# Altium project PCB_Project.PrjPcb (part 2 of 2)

## Sheet LLC.SchDoc
size 431 x 279 mm; DrawnBy: Max Wang; DocumentNumber: TIDA-010080; SheetNumber: TIDA-010080; PageSetup: Record=PageOptions¦CenterHorizontal=True¦CenterVertical=True¦PrintScale=1.00¦XCorrection=1.00¦YCorrection=1.00¦PrintKind=0¦BorderSize=5000000¦LeftOffset=0¦BottomOffset=0¦Orientation=2¦PaperLength=1000¦PaperWidth=1000¦Scale=100¦PaperSource=15¦PrintQuality=600¦MediaType=1¦DitherType=10¦PaperKind=Letter¦PrintScaleMode=1
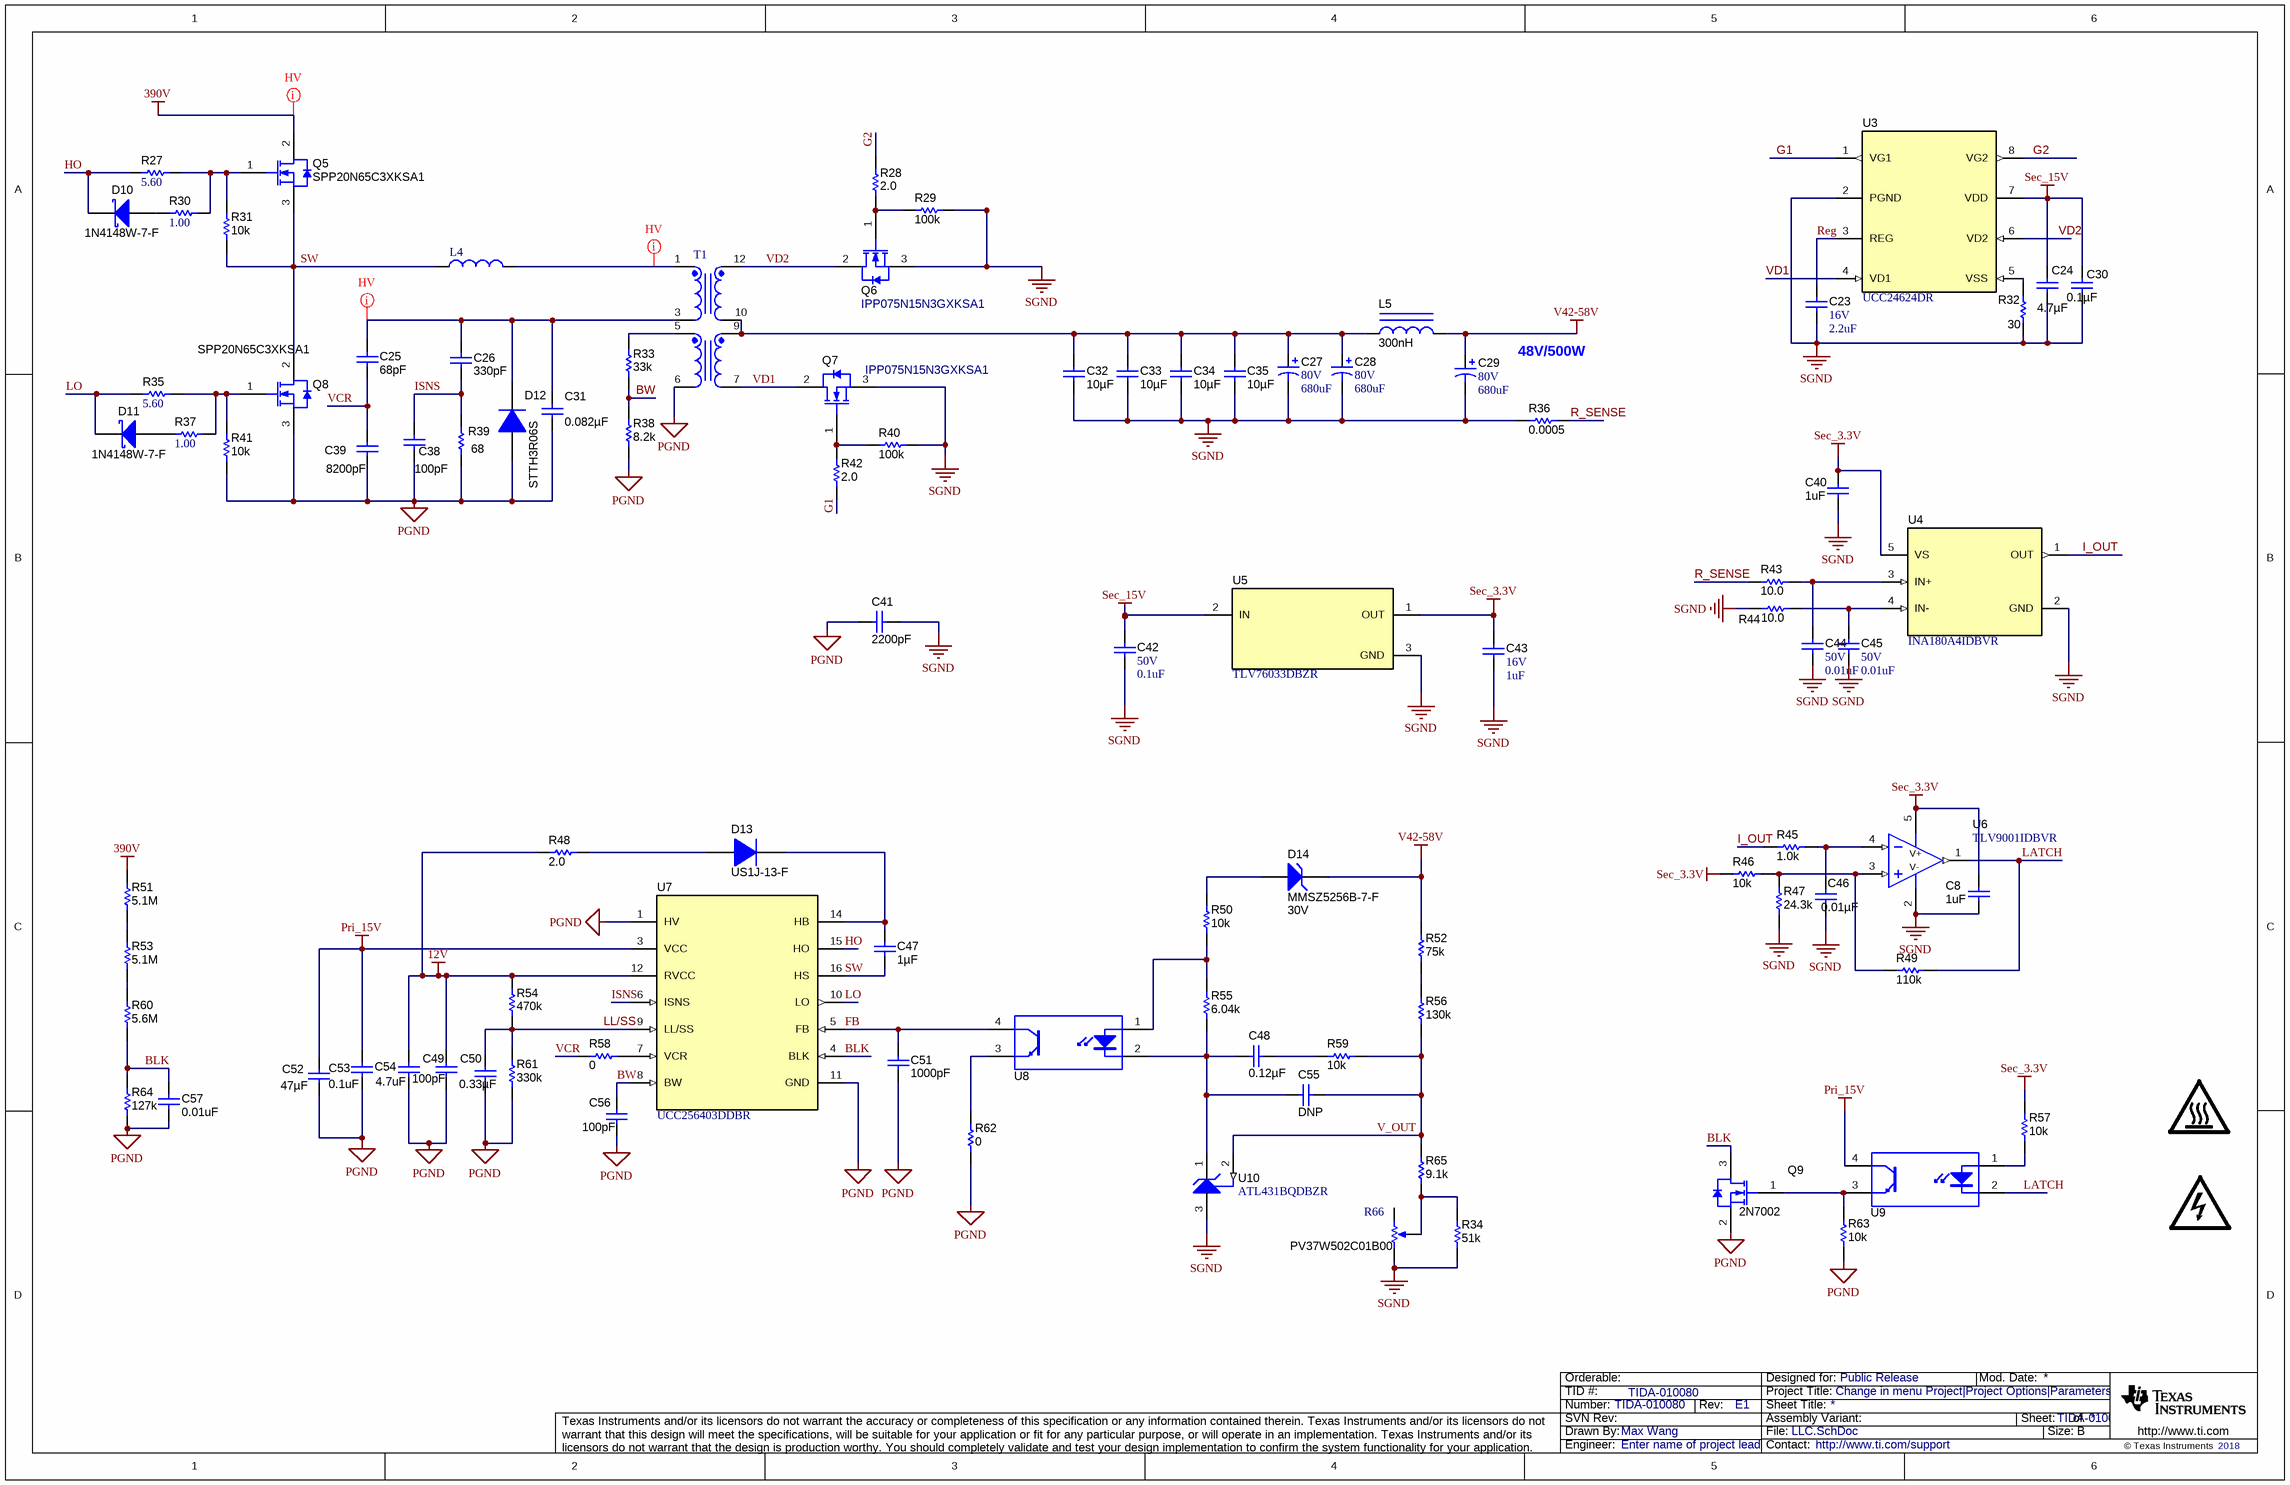
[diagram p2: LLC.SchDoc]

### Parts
(Parts that share a designator on the sheet are numbered #1, #2 ... from top to bottom, then left to right.)
C8  ValueDisplayed: 1uF  [0603]  (hidden comment: C1608X5R1E105K080AC)
C23  VDC_V: 16V  ValueDisplayed: 2.2uF  [0603]  (hidden comment: EMK107BB7225KA-T)
C24  ValueDisplayed: 4.7µF  [0603]  (hidden comment: GRM188R61E475KE11D)
C25  ValueDisplayed: 68pF  [1206]  (hidden comment: GRM31A7U3A680JW31D)
C26  ValueDisplayed: 330pF  [1206]  (hidden comment: GRM31A5C2J331JW01D)
C27  VDC_V: 80V  ValueDisplayed: 680uF  [GPA_1800x3000]  (hidden comment: EGPA800ELL681MM30S)
C28  VDC_V: 80V  ValueDisplayed: 680uF  [GPA_1800x3000]  (hidden comment: EGPA800ELL681MM30S)
C29  VDC_V: 80V  ValueDisplayed: 680uF  [GPA_1800x3000]  (hidden comment: EGPA800ELL681MM30S)
C30  ValueDisplayed: 0.1µF  [0603]  (hidden comment: GRM188R61E104KA01D)
C31  ValueDisplayed: 0.082µF  [resonant cap]  (hidden comment: R73PN2820SE00J)
C32  ValueDisplayed: 10µF  [1210_270]  (hidden comment: GRM32ER71J106KA12L)
C33  ValueDisplayed: 10µF  [1210_270]  (hidden comment: GRM32ER71J106KA12L)
C34  ValueDisplayed: 10µF  [1210_270]  (hidden comment: GRM32ER71J106KA12L)
C35  ValueDisplayed: 10µF  [1210_270]  (hidden comment: GRM32ER71J106KA12L)
C38  ValueDisplayed: 100pF  [0603]  (hidden comment: 06033C101KAT2A)
C39  ValueDisplayed: 8200pF  [0603]  (hidden comment: GRM188R71E822KA01D)
C40  ValueDisplayed: 1uF  [0603]  (hidden comment: C1608X5R1E105K080AC)
C41  ValueDisplayed: 2200pF  [AY2_950x500_Straight]  (hidden comment: AY2222M35Y5US63L7)
C42  VDC_V: 50V  ValueDisplayed: 0.1uF  [0603]  (hidden comment: GRM188R71H104KA93D)
C43  VDC_V: 16V  ValueDisplayed: 1uF  [0603]  (hidden comment: GCM188R71C105MA64D)
C44  VDC_V: 50V  ValueDisplayed: 0.01uF  [0603]  (hidden comment: GRM188R71H103KA01D)
C45  VDC_V: 50V  ValueDisplayed: 0.01uF  [0603]  (hidden comment: GRM188R71H103KA01D)
C46  ValueDisplayed: 0.01µF  [0603]  (hidden comment: GRM188R71E103KA01D)
C47  ValueDisplayed: 1µF  [1206]  (hidden comment: 12063C105KAT2A)
C48  ValueDisplayed: 0.12µF  [0603]  (hidden comment: GRM188R71E124KA01D)
C49  ValueDisplayed: 100pF  [0603]  (hidden comment: 06033C101KAT2A)
C50  ValueDisplayed: 0.33µF  [0603]  (hidden comment: GRM188R71C334KA01D)
C51  ValueDisplayed: 1000pF  [0603]  (hidden comment: 06031C102JAT2A)
C52  ValueDisplayed: 47µF  [1206]  (hidden comment: C3216JB1E476M160AC)
C53  ValueDisplayed: 0.1uF  [0603]  (hidden comment: C1608X7R1H104K080AA)
C54  ValueDisplayed: 4.7uF  [0603]  (hidden comment: GRM188R61E475KE11D)
C55  ValueDisplayed: DNP  [0603]  (hidden comment: GRM1885C1H100JA01D)
C56  ValueDisplayed: 100pF  [0603]  (hidden comment: 06033C101KAT2A)
C57  ValueDisplayed: 0.01uF  [0603]  (hidden comment: GRM188R71C103KA01D)
D10  1N4148W-7-F  [SOD-123]
D11  1N4148W-7-F  [SOD-123]
D12  STTH3R06S  [SMC]
D13  US1J-13-F  [SMA]
D14  MMSZ5256B-7-F  value 30V  [SOD-123]
L4  PQ2020  [LLC_Lr]  (value not drawn)
L5  ValueDisplayed: 300nH  [PA2607NL_7R5mm]  (hidden comment: PA2607.301NLT)
LOGO?#3  CAUTION HOT SURFACE  [IEC_HotSurface_Small]  (value not drawn)  (graphical)
LOGO?#4  DANGER HIGH VOLTAGE  [IEC_HighVoltage_Small]  (value not drawn)  (graphical)
Q5  SPP20N65C3XKSA1  [TO-220]
Q6  IPP075N15N3GXKSA1  [TO-220-3]
Q7  IPP075N15N3GXKSA1  [TO-220-3]
Q8  SPP20N65C3XKSA1  [TO-220]
Q9  2N7002  [SOT-23]
R27  ValueDisplayed: 5.60  [0805_HV]  (hidden comment: RC0805FR-075R6L)
R28  ValueDisplayed: 2.0  [0603]  (hidden comment: CRCW06032R00JNEA)
R29  ValueDisplayed: 100k  [0603]  (hidden comment: CRCW0603100KJNEA)
R30  ValueDisplayed: 1.00  [0805_HV]  (hidden comment: RC0805FR-071RL)
R31  ValueDisplayed: 10k  [0603]  (hidden comment: CRCW060310K0JNEA)
R32  ValueDisplayed: 30  [0603]  (hidden comment: CRCW060330R0JNEA)
R33  ValueDisplayed: 33k  [0603]  (hidden comment: CRCW060333K0JNEA)
R34  ValueDisplayed: 51k  [0603]  (hidden comment: CRCW060351K0JNEA)
R35  ValueDisplayed: 5.60  [0805_HV]  (hidden comment: RC0805FR-075R6L)
R36  ValueDisplayed: 0.0005  [WSL2512_-0005]  (hidden comment: WSL2512L5000FEA18)
R37  ValueDisplayed: 1.00  [0805_HV]  (hidden comment: RC0805FR-071RL)
R38  ValueDisplayed: 8.2k  [0603]  (hidden comment: CRCW06038K20JNEA)
R39  ValueDisplayed: 68  [0603]  (hidden comment: CRCW060368R0JNEA)
R40  ValueDisplayed: 100k  [0603]  (hidden comment: CRCW0603100KJNEA)
R41  ValueDisplayed: 10k  [0603]  (hidden comment: CRCW060310K0JNEA)
R42  ValueDisplayed: 2.0  [0603]  (hidden comment: CRCW06032R00JNEA)
R43  ValueDisplayed: 10.0  [0603]  (hidden comment: CRCW060310R0FKEAHP)
R44  ValueDisplayed: 10.0  [0603]  (hidden comment: CRCW060310R0FKEAHP)
R45  ValueDisplayed: 1.0k  [0603]  (hidden comment: RC0603JR-071KL)
R46  ValueDisplayed: 10k  [0603]  (hidden comment: CRCW060310K0JNEA)
R47  ValueDisplayed: 24.3k  [0603]  (hidden comment: CRCW060324K3FKEA)
R48  ValueDisplayed: 2.0  [0603]  (hidden comment: CRCW06032R00JNEA)
R49  ValueDisplayed: 110k  [0603]  (hidden comment: CRCW0603110KJNEA)
R50  ValueDisplayed: 10k  [0603]  (hidden comment: CRCW060310K0JNEA)
R51  ValueDisplayed: 5.1M  [1206]  (hidden comment: CRCW12065M10JNEA)
R52  ValueDisplayed: 75k  [0603]  (hidden comment: CRCW060375K0JNEA)
R53  ValueDisplayed: 5.1M  [1206]  (hidden comment: CRCW12065M10JNEA)
R54  ValueDisplayed: 470k  [0603]  (hidden comment: CRCW0603470KJNEA)
R55  ValueDisplayed: 6.04k  [0603]  (hidden comment: CRCW06036K04FKEA)
R56  ValueDisplayed: 130k  [0603]  (hidden comment: CRCW0603130KJNEA)
R57  ValueDisplayed: 10k  [0603]  (hidden comment: RC1608J103CS)
R58  ValueDisplayed: 0  [0603]  (hidden comment: RMCF0603ZT0R00)
R59  ValueDisplayed: 10k  [0603]  (hidden comment: CRCW060310K0JNEA)
R60  ValueDisplayed: 5.6M  [1206]  (hidden comment: CRCW12065M60JNEA)
R61  ValueDisplayed: 330k  [0603]  (hidden comment: CRCW0603330KJNEA)
R62  ValueDisplayed: 0  [0603]  (hidden comment: CRCW06030000Z0EA)
R63  ValueDisplayed: 10k  [0603]  (hidden comment: RC1608J103CS)
R64  ValueDisplayed: 127k  [0603]  (hidden comment: CRCW0603127KFKEA)
R65  ValueDisplayed: 9.1k  [0603]  (hidden comment: CRCW06039K10JNEA)
R66  PV37W502C01B00  [Bourns_PV37W]
T1  750343737  [LLC_T]  (value not drawn)
U3  PartNumber: UCC24624DR  [D0008A_N]  (hidden comment: PUCC24624D)
U4  PartNumber: INA180A4IDBVR  [DBV0005A_N]  (hidden comment: INA180A4IDBV)
U5  TLV76033DBZR  [DBZ0003A_N]
U6  TLV9001IDBVR  [DBV0005A_N]
U7  UCC256403DDBR  [DDB0014A]
U8  VO618A  [DIP-4]  (value not drawn)
U9  VO618A  [DIP-4]  (value not drawn)
U10  ATL431BQDBZR  [DBZ0003A_N]

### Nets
12V: C49.1 C54.2 R48.1 R54.2 U7.12(RVCC)
390V: Q5.2(D) R51.2
PGND: C31.2 C38.2 C39.2 C41.1 C49.2 C50.2 C51.2 C52.2 C53.2 C54.1 C56.2 C57.2 D12.2(A) Q8.3(S) Q9.2(S) R38.1 R39.1 R41.1 R61.1 R62.1 R63.2 R64.1 T1.6 U7.1(HV) U7.11(GND)
Pri_15V: C52.1 C53.1 U7.3(VCC) U9.4(C)
Sec_3.3V: C8.1 C40.1 C43.1 R46.1 R57.2 U4.5(VS) U5.1(OUT) U6.5(V+)
Sec_15V: C24.1 C30.1 C42.1 U3.7(VDD) U5.2(IN)
SGND: C8.2 C23.2 C24.2 C27.2(-) C28.2(-) C29.2(-) C30.2 C32.2 C33.2 C34.2 C35.2 C40.2 C41.2 C42.2 C43.2 C44.2 C45.2 C46.2 Q6.3(S) Q7.3(S) R29.2 R32.1 R34.1 R36.1 R40.2 R44.2 R47.1 R66.1(CCW) U3.2(PGND) U4.2(GND) U5.3(GND) U6.2(V-) U10.3(ANODE)
V42-58V: C29.1(+) D14.1(K) L5.2 R52.2
BLK: C57.1 Q9.3(D) R60.1 R64.2 U7.4(BLK)
BW: C56.1 R33.1 R38.2 U7.8(BW)
FB: C51.1 U7.5(FB) U8.4(C)
G1: R42.1 U3.1(VG1)
G2: R28.2 U3.8(VG2)
HO: D10.1(K) R27.1 U7.15(HO)
I_OUT: R45.1 U4.1(OUT)
ISNS: C26.2 C38.1 R39.2 U7.6(ISNS)
LATCH: R49.1 U6.1(OUT) U9.2(K)
LL/SS: C50.1 R54.1 R61.2 U7.9(LL/SS)
LO: D11.1(K) R35.1 U7.10(LO)
R_SENSE: R36.2 R43.2
Reg: C23.1 U3.3(REG)
SW: C47.2 L4.1 Q5.3(S) Q8.2(D) R31.1 U7.16(HS)
V_OUT: C55.1 R56.1 R59.1 R65.2 U10.2(REF)
VCR: C25.2 C39.1 R58.1
VD1: Q7.2(D) T1.7 U3.4(VD1)
VD2: Q6.2(D) T1.12 U3.6(VD2)
NetC25_1: C25.1 C26.1 C31.1 D12.1(K) T1.3
NetC27_1: C27.1(+) C28.1(+) C32.1 C33.1 C34.1 C35.1 L5.1 T1.9 T1.10
NetC44_1: C44.1 R43.1 U4.3(IN+)
NetC45_1: C45.1 R44.1 U4.4(IN-)
NetC46_1: C46.1 R45.2 U6.4(IN-)
NetC47_1: C47.1 D13.1(K) U7.14(HB)
NetC48_1: C48.1 R59.2
NetC48_2: C48.2 C55.2 R55.1 U8.2(K) U10.1(CATHODE)
NetD10_2: D10.2(A) R30.1
NetD11_2: D11.2(A) R37.1
NetD13_2: D13.2(A) R48.2
NetD14_2: D14.2(A) R50.2
NetL4_2: L4.2 T1.1
NetQ5_1: Q5.1(G) R27.2 R30.2 R31.2
NetQ6_1: Q6.1(G) R28.1 R29.1
NetQ7_1: Q7.1(G) R40.1 R42.2
NetQ8_1: Q8.1(G) R35.2 R37.2 R41.2
NetQ9_1: Q9.1(G) R63.1 U9.3(E)
NetR32_2: R32.2 U3.5(VSS)
NetR33_2: R33.2 T1.5
NetR34_2: R34.2 R65.1 R66.2(WIPER)
NetR46_2: R46.2 R47.2 R49.2 U6.3(IN+)
NetR50_1: R50.1 R55.2 U8.1(A)
NetR51_1: R51.1 R53.2
NetR52_1: R52.1 R56.2
NetR53_1: R53.1 R60.2
NetR57_1: R57.1 U9.1(A)
NetR58_2: R58.2 U7.7(VCR)
NetR62_2: R62.2 U8.3(E)

Not connected (* = marked no-connect by the designer): R66 3(CW)

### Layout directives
net class HV: 390V, NetC25_1, NetL4_2

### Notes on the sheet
- 48V/500W

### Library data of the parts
C8 C40 = CMP-0007006-5: CAP, CERM, 1 uF, 25 V, +/- 10%, X5R, 0603; Manufacturer: TDK; TaMin_C: -55°C; Polarized: N; SizeAreaWB_mm2: 4.68; Value1: Unknown; U/M: EA; Value: 1uF; TaMax_C: 85°C; SizeZ_mm: 1; SizeX_mm: 1.6; SizeY_mm: 0.8; Value2: 25V; SizeArea_mm2: 1.28; CompType: Capacitor; Cap_F: 1µF; AEC Category: Q200
C23 = CMP-0007121-4: CAP, CERM, 2.2 uF, 16 V, +/- 10%, X7R, 0603; Manufacturer: Taiyo Yuden; TaMin_C: -55°C; Polarized: N; SizeAreaWB_mm2: 4.68; Value1: Unknown; U/M: EA; Value: 2.2uF; TaMax_C: 125°C; SizeZ_mm: 1; SizeX_mm: 1.6; SizeY_mm: 0.8; SizeArea_mm2: 1.28; Cap_F: 2.2µF; AEC Category: Q200
C24 = GRM188R61E475KE11D: CAP, CERM, 4.7 µF, 25 V,+/- 10%, X5R, 0603; Manufacturer: MuRata; Polarized: N; CompType: Capacitor; Value: 4.7uF; U/M: EA; Cap_F: 0.0000047; Tolerance_%: 10; VDC_V: 25; Value2: 25V; TaMin_C: -55; TaMax_C: 85; SizeArea_mm2: 1.28; SizeAreaWB_mm2: 4.68; SizeX_mm: 1.6; SizeY_mm: 0.8; SizeZ_mm: 1; AEC Category: Q200; Green_Lifecycle: Active; Green_REACh: Passed
C25 = GRM31A7U3A680JW31D: CAP, CERM, 68 pF, 1000 V,+/- 5%, U2J, 1206; Manufacturer: MuRata; Polarized: N; CompType: Capacitor; Value: 68pF; U/M: EA; Cap_F: 0.000000000068; Tolerance_%: 5; VDC_V: 1000; Value2: 1000V; TaMin_C: -55; TaMax_C: 125; SizeArea_mm2: 5.12; SizeAreaWB_mm2: 10.92; SizeX_mm: 3.2; SizeY_mm: 1.6; SizeZ_mm: 1.35; AEC Category: Q200
C26 = GRM31A5C2J331JW01D: CAP, CERM, 330 pF, 630 V,+/- 5%, C0G/NP0, 1206; Manufacturer: MuRata; Polarized: N; CompType: Capacitor; Value: 330pF; U/M: EA; Cap_F: 0.00000000033; Tolerance_%: 5; VDC_V: 630; Value2: 630V; TaMin_C: -55; TaMax_C: 125; SizeArea_mm2: 5.12; SizeAreaWB_mm2: 10.92; SizeX_mm: 3.2; SizeY_mm: 1.6; SizeZ_mm: 1.35; AEC Category: Q200
C27-C29 = CMP-0009861-2: CAP, AL, 680 uF, 80 V, +/- 20%, 0.041 ohm, AEC-Q200 Grade 1, TH; Manufacturer: Chemi-Con; TaMin_C: -40°C; ESR_ohm: 0.041; Polarized: Y; SizeAreaWB_mm2: 400; U/M: EA; Value: 680uF; TaMax_C: 125°C; SizeZ_mm: 31.5; SizeX_mm: 18; Cap_Case: 18x30mm; SizeArea_mm2: 324; CompType: Capacitor; Cap_F: 680µF; IRMS_A: 2.58A; AEC Grade: 1; AEC Category: Q200
C30 = GRM188R61E104KA01D: CAP, CERM, 0.1 µF, 25 V,+/- 10%, X5R, 0603; Manufacturer: MuRata; Polarized: N; CompType: Capacitor; Value: 0.1uF; U/M: EA; Cap_F: 0.0000001; Tolerance_%: 10; VDC_V: 25; Value2: 25V; TaMin_C: -55; TaMax_C: 85; SizeArea_mm2: 1.28; SizeAreaWB_mm2: 4.68; SizeX_mm: 1.6; SizeY_mm: 0.8; SizeZ_mm: 1; AEC Category: Q200; Green_Lifecycle: Active; Green_REACh: Passed
C31 = R73PN2820SE00J: CAP, Film, 0.082 µF, 300 VAC/630 VDC,+/- 5%, AEC-Q200 Grade 2, TH; Manufacturer: Kemet; Polarized: N; CompType: Capacitor; Value: 0.082uF; U/M: EA; Cap_F: 0.000000082; Tolerance_%: 5; VDC_V: 630; Value2: 630V; TaMin_C: -55; TaMax_C: 105; Cap_Case: 26.5x10x18.5mm; SizeAreaWB_mm2: 342; SizeArea_mm2: 265; SizeX_mm: 26.5; SizeY_mm: 10; SizeZ_mm: 18.6; AEC Category: Q200; AEC Qualified: Y; AEC Grade: 2; VAC: 300
C32-C35 = GRM32ER71J106KA12L: CAP, CERM, 10 µF, 63 V,+/- 10%, X7R, 1210; Manufacturer: MuRata; Polarized: N; CompType: Capacitor; Value: 10uF; U/M: EA; Cap_F: 0.00001; Tolerance_%: 10; VDC_V: 63; Value2: 63V; TaMin_C: -55; TaMax_C: 125; Cap_Case: 1210; SizeArea_mm2: 8; SizeAreaWB_mm2: 14.7; SizeX_mm: 3.2; SizeY_mm: 2.5; SizeZ_mm: 2.7; AEC Category: Q200; Green_Lifecycle: Active; Green_REACh: Passed
C38 C49 C56 = 06033C101KAT2A: CAP, CERM, 100 pF, 25 V,+/- 10%, X7R, 0603; Manufacturer: AVX; Polarized: N; CompType: Capacitor; Value: 100pF; U/M: EA; Cap_F: 0.0000000001; Tolerance_%: 10; VDC_V: 25; Value2: 25V; TaMin_C: -55; TaMax_C: 125; SizeArea_mm2: 1.28; SizeAreaWB_mm2: 4.68; SizeX_mm: 1.6; SizeY_mm: 0.8; SizeZ_mm: 1; AEC Category: Q200; Green_Lifecycle: Active; Green_REACh: Passed
C39 = GRM188R71E822KA01D: CAP, CERM, 8200 pF, 25 V,+/- 10%, X7R, 0603; Manufacturer: MuRata; Polarized: N; CompType: Capacitor; Value: 8200pF; U/M: EA; Cap_F: 0.0000000082; Tolerance_%: 10; VDC_V: 25; Value2: 25V; TaMin_C: -55; TaMax_C: 125; SizeArea_mm2: 1.28; SizeAreaWB_mm2: 4.68; SizeX_mm: 1.6; SizeY_mm: 0.8; SizeZ_mm: 1; AEC Category: Q200; Green_Lifecycle: Active; Green_REACh: Passed
C41 = AY2222M35Y5US63L7: CAP, CERM, 2200 pF, X1 440 VAC/Y2 300 VAC, +/- 20%, Y5U, AEC-Q200 Grade 1, D9.5xT5mm; Manufacturer: Vishay-Bccomponents; Polarized: N; CompType: Capacitor; Value: 2200pF; U/M: EA; Cap_F: 0.0000000022; Tolerance_%: 20; TaMin_C: -55; TaMax_C: 125; Cap_Case: 9.5x5mm; SizeArea_mm2: 47.5; SizeAreaWB_mm2: 80.5; SizeX_mm: 9.5; SizeY_mm: 5; SizeZ_mm: 14.5; AEC Category: Q200; AEC Qualified: Y; AEC Grade: 1; AC_Safety: X1Y2; VAC_X: 440; VAC_Y: 300
C42 = CMP-0007434-4: CAP, CERM, 0.1 uF, 50 V, +/- 10%, X7R, 0603; Manufacturer: MuRata; TaMin_C: -55°C; Polarized: N; SizeAreaWB_mm2: 4.68; Value1: Unknown; U/M: EA; Value: 0.1uF; TaMax_C: 125°C; SizeZ_mm: 1; SizeX_mm: 1.6; SizeY_mm: 0.8; SizeArea_mm2: 1.28; CompType: Capacitor; Cap_F: 100nF; AEC Category: Q200
C43 = CMP-0007137-5: CAP, CERM, 1 uF, 16 V, +/- 20%, X7R, AEC-Q200 Grade 1, 0603; Manufacturer: MuRata; TaMin_C: -55°C; Polarized: N; SizeAreaWB_mm2: 4.68; Value1: Unknown; U/M: EA; Value: 1uF; TaMax_C: 125°C; SizeZ_mm: 1; SizeX_mm: 1.6; SizeY_mm: 0.8; SizeArea_mm2: 1.28; CompType: Capacitor; AEC Qualified: Y; Cap_F: 1µF; AEC Category: Q200
C44 C45 = CMP-0007433-4: CAP, CERM, 0.01 uF, 50 V, +/- 10%, X7R, 0603; Manufacturer: MuRata; TaMin_C: -55°C; Polarized: N; SizeAreaWB_mm2: 4.68; Value1: Unknown; U/M: EA; Value: 0.01uF; TaMax_C: 125°C; SizeZ_mm: 1; SizeX_mm: 1.6; SizeY_mm: 0.8; SizeArea_mm2: 1.28; CompType: Capacitor; Cap_F: 10nF; AEC Category: Q200
C46 = GRM188R71E103KA01D: CAP, CERM, 0.01 µF, 25 V,+/- 10%, X7R, 0603; Manufacturer: MuRata; Polarized: N; CompType: Capacitor; Value: 0.01uF; U/M: EA; Cap_F: 0.00000001; Tolerance_%: 10; VDC_V: 25; Value2: 25V; TaMin_C: -55; TaMax_C: 125; SizeArea_mm2: 1.28; SizeAreaWB_mm2: 4.68; SizeX_mm: 1.6; SizeY_mm: 0.8; SizeZ_mm: 1; AEC Category: Q200; Green_Lifecycle: Active; Green_REACh: Passed
C47 = 12063C105KAT2A: CAP, CERM, 1 µF, 25 V,+/- 10%, X7R, 1206; Manufacturer: AVX; Polarized: N; CompType: Capacitor; Value: 1uF; U/M: EA; Cap_F: 0.000001; Tolerance_%: 10; ESR_ohm: 0.013; Value1: 0.013 ohm; VDC_V: 25; Value2: 25V; TaMin_C: -55; TaMax_C: 125; SizeArea_mm2: 5.12; SizeAreaWB_mm2: 10.92; SizeX_mm: 3.2; SizeY_mm: 1.6; SizeZ_mm: 1.35; AEC Category: Q200; Green_Lifecycle: Active; Green_REACh: Passed
C48 = GRM188R71E124KA01D: CAP, CERM, 0.12 µF, 25 V,+/- 10%, X7R, 0603; Manufacturer: MuRata; Polarized: N; CompType: Capacitor; Value: 0.12uF; U/M: EA; Cap_F: 0.00000012; Tolerance_%: 10; VDC_V: 25; Value2: 25V; TaMin_C: -55; TaMax_C: 125; SizeArea_mm2: 1.28; SizeAreaWB_mm2: 4.68; SizeX_mm: 1.6; SizeY_mm: 0.8; SizeZ_mm: 1; AEC Category: Q200
C50 = GRM188R71C334KA01D: CAP, CERM, 0.33 µF, 16 V,+/- 10%, X7R, 0603; Manufacturer: MuRata; Polarized: N; CompType: Capacitor; Value: 0.33uF; U/M: EA; Cap_F: 0.00000033; Tolerance_%: 10; VDC_V: 16; Value2: 16V; TaMin_C: -55; TaMax_C: 125; SizeArea_mm2: 1.28; SizeAreaWB_mm2: 4.68; SizeX_mm: 1.6; SizeY_mm: 0.8; SizeZ_mm: 1; AEC Category: Q200; Green_Lifecycle: Active; Green_REACh: Passed
C51 = 06031C102JAT2A: CAP, CERM, 1000 pF, 100 V,+/- 5%, X7R, 0603; Manufacturer: AVX; Polarized: N; CompType: Capacitor; Value: 1000pF; U/M: EA; Cap_F: 0.000000001; Tolerance_%: 5; ESR_ohm: 0.276; Value1: 0.276 ohm; VDC_V: 100; Value2: 100V; TaMin_C: -55; TaMax_C: 125; SizeArea_mm2: 1.28; SizeAreaWB_mm2: 4.68; SizeX_mm: 1.6; SizeY_mm: 0.8; SizeZ_mm: 1; AEC Category: Q200; Green_Lifecycle: Active; Green_REACh: Passed
C52 = C3216JB1E476M160AC: CAP, CERM, 47 µF, 25 V,+/- 20%, JB, 1206; Manufacturer: TDK; Polarized: N; CompType: Capacitor; Value: 47uF; U/M: EA; Cap_F: 0.000047; Tolerance_%: 20; VDC_V: 25; Value2: 25V; TaMin_C: -55; TaMax_C: 85; SizeArea_mm2: 5.12; SizeAreaWB_mm2: 10.92; SizeX_mm: 3.2; SizeY_mm: 1.6; SizeZ_mm: 1.35; AEC Category: Q200
C53 = CMP-0007044-5: CAP, CERM, 0.1 uF, 50 V, +/- 10%, X7R, 0603; Manufacturer: TDK; TaMin_C: -55°C; ESR_ohm: 0.0296; Polarized: N; SizeAreaWB_mm2: 4.68; Value1: 0.0296 ohm; U/M: EA; Value: 0.1uF; TaMax_C: 125°C; SizeZ_mm: 1; SizeX_mm: 1.6; SizeY_mm: 0.8; Value2: 50V; SizeArea_mm2: 1.28; CompType: Capacitor; Cap_F: 100nF; IRMS_A: 9.7199dA; AEC Category: Q200
C54 = CMP-0007347-5: CAP, CERM, 4.7 uF, 25 V, +/- 10%, X5R, 0603; Manufacturer: MuRata; TaMin_C: -55°C; Polarized: N; SizeAreaWB_mm2: 4.68; Value1: Unknown; U/M: EA; Value: 4.7uF; TaMax_C: 85°C; SizeZ_mm: 1; SizeX_mm: 1.6; SizeY_mm: 0.8; Value2: 25V; SizeArea_mm2: 1.28; CompType: Capacitor; Cap_F: 4.7µF; AEC Category: Q200
C55 = GRM1885C1H100JA01D: CAP, CERM, 10 pF, 50 V,+/- 5%, C0G/NP0, 0603; Manufacturer: MuRata; Polarized: N; CompType: Capacitor; Value: 10pF; U/M: EA; Cap_F: 0.00000000001; Tolerance_%: 5; VDC_V: 50; Value2: 50V; TaMin_C: -55; TaMax_C: 125; SizeArea_mm2: 1.28; SizeAreaWB_mm2: 4.68; SizeX_mm: 1.6; SizeY_mm: 0.8; SizeZ_mm: 1; AEC Category: Q200; Green_Lifecycle: Active; Green_REACh: Passed
C57 = CMP-0007377-4: CAP, CERM, 0.01 uF, 16 V, +/- 10%, X7R, 0603; Manufacturer: MuRata; TaMin_C: -55°C; Polarized: N; SizeAreaWB_mm2: 4.68; Value1: Unknown; U/M: EA; Value: 0.01uF; TaMax_C: 125°C; SizeZ_mm: 1; SizeX_mm: 1.6; Value2: 16V; SizeArea_mm2: 1.28; CompType: Capacitor; Cap_F: 10nF; AEC Category: Q200; SizeY_mm: 0.8
D10 D11 = CMP-0028358-1: Diode, Schottky, 70 V, 0.015 A, SOD-123; Manufacturer: Diodes Inc.; PartNumber: 1N5711W-7-F; Io_A: 15mA; Green_Lifecycle: Not Set; SizeAreaWB_mm2: 13.095; Vr_V: 70V; Green_REACh: Incomplete; Value1: 0.015A; U/M: EA; Value: 70V; SizeZ_mm: 1.35; SizeX_mm: 3.85; SizeY_mm: 1.7; Vf_V: 1V; SizeArea_mm2: 6.545; AEC Category: Q101
D12 = MURS360T3G: Diode, Ultrafast, 600 V, 3 A, SMC; Manufacturer: ST; U/M: EA; Vf_V: 1.25; Value: 600V; Value1: 3A; Value2: 1.25V; Io_A: 3; Vr_V: 600; TJmax_C: 175; RJC_CperW: 11; SizeAreaWB_mm2: 83.2686; SizeArea_mm2: 50.5686; SizeX_mm: 8.13; SizeY_mm: 6.22; SizeZ_mm: 2.6; AEC Category: Q101; Green_Lifecycle: Active; Green_REACh: Passed
D13 = US1J-13-F: Diode, Ultrafast, 600 V, 1 A, SMA; Manufacturer: Diodes Inc.; U/M: EA; Vf_V: 1.7; Value: 600V; Value1: 1A; Value2: 1.7V; Io_A: 1; Vr_V: 600; TJmax_C: 150; SizeAreaWB_mm2: 37.3428; SizeArea_mm2: 16.3228; SizeX_mm: 5.59; SizeY_mm: 2.92; SizeZ_mm: 2.87; AEC Category: Q101; Green_Lifecycle: Active; Green_REACh: Passed
D14 = MMSZ5256B-7-F: Diode, Zener, 30 V, 500 mW, SOD-123; Manufacturer: Diodes Inc.; SymbolCreator: a0412235; U/M: EA; Power_W: 0.5; Vz_V: 30; Value1: 0.5W; RJA_CperW: 350; SizeAreaWB_mm2: 13.095; SizeArea_mm2: 6.545; SizeX_mm: 3.85; SizeY_mm: 1.7; SizeZ_mm: 1.35; AEC Category: Q101
L4 = Inductor: Part Number: 750344650; Code_IEC: 1005
L5 = CMP-0062077-1: Inductor, Ferrite, 300 nH, 32 A, 0.00031 ohm, SMD; Manufacturer: Pulse Engineering; Isat: 32A @ 20% inductance drop; Irms: 41A @ 40C rise; SizeAreaWB_mm2: 118.7915; DCR_ohm: 310µ; Value: 300nH; Imax_A: 32A; SizeZ_mm: 7.5; SizeX_mm: 7.65; SizeY_mm: 10.31; SizeArea_mm2: 78.8715; AEC Qualified: N; AEC Category: Q200
LOGO?#3 = IEC_HotSurface: IEC 61010-1 Hot Surface Warning; SymbolCreator: a0412235
LOGO?#4 = IEC_HighVoltage: IEC 61010-1 High Voltage Warning; SymbolCreator: a0412235
Q5 Q8 = SPP20N65C3XKSA1: MOSFET, N-CH, 650 V, 20.7 A, TO-220AB; Manufacturer: Infineon Technologies; Alternate Manufacturer: None; U/M: EA; ChType: N; Value: 650V; VdsMax_V: 650; Value1: ? ohm; Value2: 87 nC; QgTyp_nC: 87; Vgs_V: 20; IdsMax_A: 20.7; SizeAreaWB_mm2: 79.3; SizeArea_mm2: 45.9; SizeX_mm: 10.2; SizeY_mm: 4.5; SizeZ_mm: 19.4; AEC Category: Q101
Q6 Q7 = CMP-0860023-1: MOSFET, N-CH, 150 V, 100 A,; Manufacturer: Infineon Technologies; Alternate Manufacturer: None; AEC Category: Q101; Value1: ? ohm; ChType: N; SizeArea_mm2: 86.0552; SizeAreaWB_mm2: 127.3152; ChMode: Enhancement; Value: 150V; QgTyp_nC: 70; IdsMax_A: 100A; SizeX_mm: 8.47; Value2: 70 nC; Vgs_V: 20V; SizeZ_mm: 20.68; SizeY_mm: 10.16
Q9 = 2N7002: MOSFET, N-CH, 60 V, 115 A, SOT-23; Manufacturer: Fairchild Semiconductor; Alternate Manufacturer: None; U/M: EA; ChType: N; Value: 60V; VdsMax_V: 60; Value1: ? ohm; Value2: ? nC; Vgs_V: 20; IdsMax_A: 115; SizeAreaWB_mm2: 14; SizeArea_mm2: 7.5; SizeX_mm: 2.5; SizeY_mm: 3; SizeZ_mm: 1.1; AEC Category: Q101; Green_Lifecycle: Active; Green_REACh: Passed
R27 R35 = CMP-0021945-2: RES, 5.60, 1%, 0.125 W, 0805; Manufacturer: Yageo America; Power_W: 125mW; TempCo: 200 ppm/C; Value_Code: 5R60; U/M: EA; Value: 5.60; Res_ohm: 5.6; SizeX_mm: 2; SizeY_mm: 1.25; SizeZ_mm: 1.45; Value2: 0.125W; SizeArea_mm2: 2.5; CompType: Resistor; VDC_V: 150V; AEC Category: Q200
R28 R42 R48 = CRCW06032R00JNEA: RES, 2.0, 5%, 0.1 W, 0603; Manufacturer: Vishay-Dale; CompType: Resistor; Value: 2.0; Res_ohm: 2; Value_Code: 2R00; Tolerance_%: 5; Power_W: 0.1; Value2: 0.1W; VDC_V: 75; TempCo: 200 ppm/C; SizeArea_mm2: 1.28; SizeX_mm: 1.6; SizeY_mm: 0.8; SizeZ_mm: 1; EIA_Code: E24; U/M: EA; AEC Category: Q200; Green_Lifecycle: Active; Green_REACh: Passed
R29 R40 = CRCW0603100KJNEA: RES, 100 k, 5%, 0.1 W, 0603; Manufacturer: Vishay-Dale; CompType: Resistor; Value: 100k; Res_ohm: 100000; Tolerance_%: 5; Power_W: 0.1; Value2: 0.1W; VDC_V: 75; TempCo: 200 ppm/C; SizeArea_mm2: 1.28; SizeX_mm: 1.6; SizeY_mm: 0.8; SizeZ_mm: 1; EIA_Code: E24; U/M: EA; AEC Category: Q200; Green_Lifecycle: Active; Green_REACh: Passed
R30 R37 = CMP-0021894-2: RES, 1.00, 1%, 0.125 W, 0805; Manufacturer: Yageo America; Power_W: 125mW; TempCo: 200 ppm/C; Value_Code: 1R00; U/M: EA; Value: 1.00; EIA_Code: E96; Res_ohm: 1; SizeX_mm: 2; SizeY_mm: 1.25; SizeZ_mm: 1.45; Value2: 0.125W; SizeArea_mm2: 2.5; CompType: Resistor; VDC_V: 150V; AEC Category: Q200
R31 R41 R46 R50 R59 = CRCW060310K0JNEA: RES, 10 k, 5%, 0.1 W, 0603; Manufacturer: Vishay-Dale; CompType: Resistor; Value: 10k; Res_ohm: 10000; Value_Code: 10k0; Tolerance_%: 5; Power_W: 0.1; Value2: 0.1W; VDC_V: 75; TempCo: 200 ppm/C; SizeArea_mm2: 1.28; SizeX_mm: 1.6; SizeY_mm: 0.8; SizeZ_mm: 1; EIA_Code: E24; U/M: EA; AEC Category: Q200; Green_Lifecycle: Active; Green_REACh: Passed
R32 = CRCW060330R0JNEA: RES, 30, 5%, 0.1 W, 0603; Manufacturer: Vishay-Dale; CompType: Resistor; Value: 30; Value_Code: 30R0; Tolerance_%: 5; Power_W: 0.1; Value2: 0.1W; VDC_V: 75; TempCo: 200 ppm/C; SizeArea_mm2: 1.28; SizeX_mm: 1.6; SizeY_mm: 0.8; SizeZ_mm: 1; EIA_Code: E24; U/M: EA; AEC Category: Q200
R33 = CRCW060333K0JNEA: RES, 33 k, 5%, 0.1 W, 0603; Manufacturer: Vishay-Dale; CompType: Resistor; Value: 33k; Res_ohm: 33000; Value_Code: 33k0; Tolerance_%: 5; Power_W: 0.1; Value2: 0.1W; VDC_V: 75; TempCo: 200 ppm/C; SizeArea_mm2: 1.28; SizeX_mm: 1.6; SizeY_mm: 0.8; SizeZ_mm: 1; EIA_Code: E24; U/M: EA; AEC Category: Q200; Green_Lifecycle: Active; Green_REACh: Passed
R34 = CRCW060351K0JNEA: RES, 51 k, 5%, 0.1 W, 0603; Manufacturer: Vishay-Dale; CompType: Resistor; Value: 51k; Res_ohm: 51000; Value_Code: 51k0; Tolerance_%: 5; Power_W: 0.1; Value2: 0.1W; VDC_V: 75; TempCo: 200 ppm/C; SizeArea_mm2: 1.28; SizeX_mm: 1.6; SizeY_mm: 0.8; SizeZ_mm: 1; EIA_Code: E24; U/M: EA; AEC Category: Q200; Green_Lifecycle: Active; Green_REACh: Passed
R36 = CMP-0015849-2: RES, 0.0005, 1%, 2 W, 2512; Manufacturer: Vishay-Dale; Power_W: 2W; TempCo: 400 ppm/C; Value_Code: L5000; U/M: EA; Value: 0.0005; Res_ohm: 500µ; SizeX_mm: 6.35; SizeY_mm: 3.18; SizeZ_mm: 0.89; SizeArea_mm2: 20.193; AEC Qualified: N; AEC Category: Q200
R38 = CRCW06038K20JNEA: RES, 8.2 k, 5%, 0.1 W, 0603; Manufacturer: Vishay-Dale; CompType: Resistor; Value: 8.2k; Res_ohm: 8200; Value_Code: 8k20; Tolerance_%: 5; Power_W: 0.1; Value2: 0.1W; VDC_V: 75; TempCo: 200 ppm/C; SizeArea_mm2: 1.28; SizeX_mm: 1.6; SizeY_mm: 0.8; SizeZ_mm: 1; EIA_Code: E24; U/M: EA; AEC Category: Q200; Green_Lifecycle: Active; Green_REACh: Passed
R39 = CRCW060368R0JNEA: RES, 68, 5%, 0.1 W, 0603; Manufacturer: Vishay-Dale; CompType: Resistor; Value: 68; Value_Code: 68R0; Tolerance_%: 5; Power_W: 0.1; Value2: 0.1W; VDC_V: 75; TempCo: 200 ppm/C; SizeArea_mm2: 1.28; SizeX_mm: 1.6; SizeY_mm: 0.8; SizeZ_mm: 1; EIA_Code: E24; U/M: EA; AEC Category: Q200; Green_Lifecycle: Active; Green_REACh: Passed
R43 R44 = CMP-0022004-4: RES, 10.0, 1%, 0.25 W, AEC-Q200 Grade 0, 0603; Manufacturer: Vishay-Dale; Power_W: 250mW; TempCo: 100 ppm/C; Value_Code: 10R0; Value: 10.0; EIA_Code: E96; Res_ohm: 10; SizeX_mm: 1.6; SizeY_mm: 0.8; SizeZ_mm: 1; Value2: 0.25W; SizeArea_mm2: 1.28; AEC Qualified: Y; VDC_V: 75V; AEC Category: Q200; AEC Grade: 0
R45 = RC0603JR-071KL: RES, 1.0 k, 5%, 0.1 W, 0603; Manufacturer: Yageo America; CompType: Resistor; Value: 1.0k; Res_ohm: 1000; Value_Code: 1k00; Tolerance_%: 5; Power_W: 0.1; Value2: 0.1W; VDC_V: 50; TempCo: 100 ppm/C; SizeArea_mm2: 1.28; SizeX_mm: 1.6; SizeY_mm: 0.8; SizeZ_mm: 1; EIA_Code: E24; U/M: EA; AEC Category: Q200; Green_Lifecycle: Active; Green_REACh: Passed
R47 = CRCW060324K3FKEA: RES, 24.3 k, 1%, 0.1 W, 0603; Manufacturer: Vishay-Dale; CompType: Resistor; Value: 24.3k; Res_ohm: 24300; Value_Code: 24k3; Tolerance_%: 1; Power_W: 0.1; Value2: 0.1W; VDC_V: 75; TempCo: 100 ppm/C; SizeArea_mm2: 1.28; SizeX_mm: 1.6; SizeY_mm: 0.8; EIA_Code: E96; U/M: EA; AEC Category: Q200; Green_Lifecycle: Active; Green_REACh: Passed
R49 = CRCW0603110KJNEA: RES, 110 k, 5%, 0.1 W, 0603; Manufacturer: Vishay-Dale; CompType: Resistor; Value: 110k; Res_ohm: 110000; Tolerance_%: 5; Power_W: 0.1; Value2: 0.1W; VDC_V: 75; TempCo: 200 ppm/C; SizeArea_mm2: 1.28; SizeX_mm: 1.6; SizeY_mm: 0.8; SizeZ_mm: 1; EIA_Code: E24; U/M: EA; AEC Category: Q200
R51 R53 = CRCW12065M10JNEA: RES, 5.1 M, 5%, 0.25 W, 1206; Manufacturer: Vishay-Dale; CompType: Resistor; Value: 5.1Meg; Res_ohm: 5100000; Value_Code: 5M10; Tolerance_%: 5; Power_W: 0.25; Value2: 0.25W; VDC_V: 200; TempCo: 200 ppm/C; SizeArea_mm2: 5.12; SizeX_mm: 3.2; SizeY_mm: 1.6; SizeZ_mm: 1.35; EIA_Code: E24; U/M: EA; AEC Category: Q200; Green_Lifecycle: Active; Green_REACh: Passed
R52 = CRCW060375K0JNEA: RES, 75 k, 5%, 0.1 W, 0603; Manufacturer: Vishay-Dale; CompType: Resistor; Value: 75k; Res_ohm: 75000; Value_Code: 75k0; Tolerance_%: 5; Power_W: 0.1; Value2: 0.1W; VDC_V: 75; TempCo: 200 ppm/C; SizeArea_mm2: 1.28; SizeX_mm: 1.6; SizeY_mm: 0.8; SizeZ_mm: 1; EIA_Code: E24; U/M: EA; AEC Category: Q200
R54 = CRCW0603470KJNEA: RES, 470 k, 5%, 0.1 W, 0603; Manufacturer: Vishay-Dale; CompType: Resistor; Value: 470k; Res_ohm: 470000; Tolerance_%: 5; Power_W: 0.1; Value2: 0.1W; VDC_V: 75; TempCo: 200 ppm/C; SizeArea_mm2: 1.28; SizeX_mm: 1.6; SizeY_mm: 0.8; SizeZ_mm: 1; EIA_Code: E24; U/M: EA; AEC Category: Q200; Green_Lifecycle: Active; Green_REACh: Passed
R55 = CRCW06036K04FKEA: RES, 6.04 k, 1%, 0.1 W, 0603; Manufacturer: Vishay-Dale; CompType: Resistor; Value: 6.04k; Res_ohm: 6040; Value_Code: 6k04; Tolerance_%: 1; Power_W: 0.1; Value2: 0.1W; VDC_V: 75; TempCo: 100 ppm/C; SizeArea_mm2: 1.28; SizeX_mm: 1.6; SizeY_mm: 0.8; EIA_Code: E96; U/M: EA; AEC Category: Q200; Green_Lifecycle: Active; Green_REACh: Passed
R56 = CRCW0603130KJNEA: RES, 130 k, 5%, 0.1 W, 0603; Manufacturer: Vishay-Dale; CompType: Resistor; Value: 130k; Res_ohm: 130000; Tolerance_%: 5; Power_W: 0.1; Value2: 0.1W; VDC_V: 75; TempCo: 200 ppm/C; SizeArea_mm2: 1.28; SizeX_mm: 1.6; SizeY_mm: 0.8; SizeZ_mm: 1; EIA_Code: E24; U/M: EA; AEC Category: Q200; Green_Lifecycle: Active; Green_REACh: Passed
R57 R63 = RC1608J103CS: RES, 10 k, 5%, 0.1 W, 0603; Manufacturer: Samsung Electro-Mechanics; CompType: Resistor; Value: 10k; Res_ohm: 10000; Value_Code: 10k0; Tolerance_%: 5; Power_W: 0.1; Value2: 0.1W; VDC_V: 31; TempCo: 100 ppm/C; SizeArea_mm2: 1.28; SizeX_mm: 1.6; SizeY_mm: 0.8; SizeZ_mm: 1; EIA_Code: E24; U/M: EA; AEC Category: Q200; AEC Qualified: N; Green_Lifecycle: Active; Green_REACh: Passed
R58 = RMCF0603ZT0R00: RES, 0, 1%, 0.1 W, AEC-Q200 Grade 0, 0603; Manufacturer: Stackpole Electronics Inc; CompType: Resistor; Value: 0; Tolerance_%: 1; Power_W: 0.1; Value2: 0.1W; TempCo: ppm/C; SizeArea_mm2: 1.28; SizeX_mm: 1.6; SizeY_mm: 0.8; U/M: EA; AEC Category: Q200; AEC Qualified: Y; Green_Lifecycle: Active; Green_REACh: Passed
R60 = CRCW12065M60JNEA: RES, 5.6 M, 5%, 0.25 W, 1206; Manufacturer: Vishay-Dale; CompType: Resistor; Value: 5.6Meg; Res_ohm: 5600000; Value_Code: 5M60; Tolerance_%: 5; Power_W: 0.25; Value2: 0.25W; VDC_V: 200; TempCo: 200 ppm/C; SizeArea_mm2: 5.12; SizeX_mm: 3.2; SizeY_mm: 1.6; SizeZ_mm: 1.35; EIA_Code: E24; U/M: EA; AEC Category: Q200
R61 = CRCW0603330KJNEA: RES, 330 k, 5%, 0.1 W, 0603; Manufacturer: Vishay-Dale; CompType: Resistor; Value: 330k; Res_ohm: 330000; Tolerance_%: 5; Power_W: 0.1; Value2: 0.1W; VDC_V: 75; TempCo: 200 ppm/C; SizeArea_mm2: 1.28; SizeX_mm: 1.6; SizeY_mm: 0.8; SizeZ_mm: 1; EIA_Code: E24; U/M: EA; AEC Category: Q200; Green_Lifecycle: Active; Green_REACh: Passed
R62 = CRCW06030000Z0EA: RES, 0, 5%, 0.1 W, 0603; Manufacturer: Vishay-Dale; CompType: Resistor; Value: 0; Value_Code: 0000; Tolerance_%: 5; Power_W: 0.1; Value2: 0.1W; VDC_V: 75; TempCo: 200 ppm/C; SizeArea_mm2: 1.28; SizeX_mm: 1.6; SizeY_mm: 0.8; SizeZ_mm: 1; EIA_Code: E24; U/M: EA; AEC Category: Q200; Green_Lifecycle: Active; Green_REACh: Passed
R64 = CRCW0603127KFKEA: RES, 127 k, 1%, 0.1 W, 0603; Manufacturer: Vishay-Dale; CompType: Resistor; Value: 127k; Res_ohm: 127000; Tolerance_%: 1; Power_W: 0.1; Value2: 0.1W; VDC_V: 75; TempCo: 100 ppm/C; SizeArea_mm2: 1.28; SizeX_mm: 1.6; SizeY_mm: 0.8; EIA_Code: E96; U/M: EA; AEC Category: Q200; Green_Lifecycle: Active; Green_REACh: Passed
R65 = CRCW06039K10JNEA: RES, 9.1 k, 5%, 0.1 W, 0603; Manufacturer: Vishay-Dale; CompType: Resistor; Value: 9.1k; Res_ohm: 9100; Value_Code: 9k10; Tolerance_%: 5; Power_W: 0.1; Value2: 0.1W; VDC_V: 75; TempCo: 200 ppm/C; SizeArea_mm2: 1.28; SizeX_mm: 1.6; SizeY_mm: 0.8; SizeZ_mm: 1; EIA_Code: E24; U/M: EA; AEC Category: Q200; Green_Lifecycle: Active; Green_REACh: Passed
R66 = CMP-0001795-2: Trimmer Potentiometer, Lead Sealed Type Multiturn PV37 Series, TH; Manufacturer: Bourns; Value: 5k Ohm; SizeX_mm: 6.71; SizeY_mm: 4.5; SizeZ_mm: 8.39; SizeArea_mm2: 30.195; SizeAreaWB_mm2: 56.615
T1 = 760895431: WE-LLCR Resonant Converter, size PQ3232, 155uH, 16:4:4:1 , 500W; Part Number: 750344508; Input Voltage: 360-400 V DC; Inductance: 600uH; Turns Ratio: 35:2:2:3
U3 = CMP-0079610-1: High Performance Synchronous Rectifier Driver for LLC Resonant Converter, D0008A (SOIC-8); Alternate Manufacturer: Texas Instruments; SizeAreaWB_mm2: 56.58; SizeZ_mm: 1.75; SizeX_mm: 4.9; SizeY_mm: 6.2; SizeArea_mm2: 30.38; CompType: IC; AEC Qualified: N; AEC Category: Q200
U4 = CMP-0013052-2: Low- and High-Side Measurement, Multichannel, Voltage Output, Current-Sense Amplifier, DBV0005A (SOT-5); Manufacturer: Texas Instruments; SizeX_mm: 2.8; SizeY_mm: 2.9; CompType: IC; SizeZ_mm: 1.45; SizeArea_mm2: 8.12; SizeAreaWB_mm2: 14.82; U/M: EA
U5 = CMP-0074893-1: 100-mA, 30-V, Fixed-Output, Linear-Voltage Regulator, DBZ0003A (SOT-23-3); Alternate PartNumber: TLV76033DBZT; Alternate Manufacturer: Texas Instruments; SizeAreaWB_mm2: 14.0; SizeZ_mm: 1.12; SizeX_mm: 2.5; SizeY_mm: 3.0; SizeArea_mm2: 7.5; CompType: IC; AEC Qualified: N; AEC Category: Q200
U6 = CMP-0081550-1: Low-Power, Rail-to-Rail In and Out, 1-MHz Operational Amplifier, DBV0005A (SOT-23-5); Alternate PartNumber: TLV9001IDBVT; Alternate Manufacturer: Texas Instruments; SizeAreaWB_mm2: 14.82; SizeZ_mm: 1.45; SizeX_mm: 2.8; SizeY_mm: 2.9; SizeArea_mm2: 8.12; CompType: IC; AEC Qualified: N; AEC Category: Q200
U7 = CMP-0077204-4: LLC Resonant Controller Enabling Low Standby Power, DDB0014A (SOIC-14); Alternate Manufacturer: Texas Instruments; SizeAreaWB_mm2: 95.2; SizeZ_mm: 1.75; SizeX_mm: 6.0; SizeY_mm: 9.9; SizeArea_mm2: 59.4; CompType: IC; AEC Qualified: N; AEC Category: Q200; Rating: Catalog
U8 U9 = VO618A: Optocoupler, 5.3 kV, 50-600% CTR, TH; Manufacturer: Vishay-Semiconductor; CTR (Min): 50%; CTR (Max): 600%; Voltage_Isolation_Vrms: 5300V; SizeAreaWB_mm2: 71.064; SizeArea_mm2: 40.304; SizeX_mm: 8.8; SizeY_mm: 4.58; SizeZ_mm: 5
U10 = CMP-0066200-1: 2.5V Low Iq Adjustable Precision Shunt Regulator, DBZ0003A (SOT-23-3); Alternate PartNumber: ATL431BQDBZT; Alternate Manufacturer: Texas Instruments; Green_Lifecycle: Active; SizeAreaWB_mm2: 14.0; Green_REACh: Passed; U/M: EA; SizeZ_mm: 1.12; SizeX_mm: 2.5; SizeY_mm: 3.0; SizeArea_mm2: 7.5; CompType: IC

## Sheet PCB_Project_EVM_Hardware.SchDoc
size 431 x 279 mm; Date: Not shown in title block; ApprovedBy: Not shown in title block; CheckedBy: Not shown in title block; Author: Not shown in title block; CompanyName: Not shown in title block; Engineer: Not shown in title block; Organization: Not shown in title block; Address1: Not shown in title block; Address2: Not shown in title block; Address3: Not shown in title block; Address4: Not shown in title block; DocumentNumber: 1; Revision: Use project parameter SCH_Rev; SheetNumber: 3; SheetTotal: 3; PageSetup: Record=PageOptions¦CenterHorizontal=True¦CenterVertical=True¦PrintScale=1.00¦XCorrection=1.00¦YCorrection=1.00¦PrintKind=0¦BorderSize=5000000¦LeftOffset=0¦BottomOffset=0¦Orientation=2¦PaperLength=1000¦PaperWidth=1000¦Scale=100¦PaperSource=15¦PrintQuality=600¦MediaType=1¦DitherType=10¦PaperKind=Letter¦PrintScaleMode=1
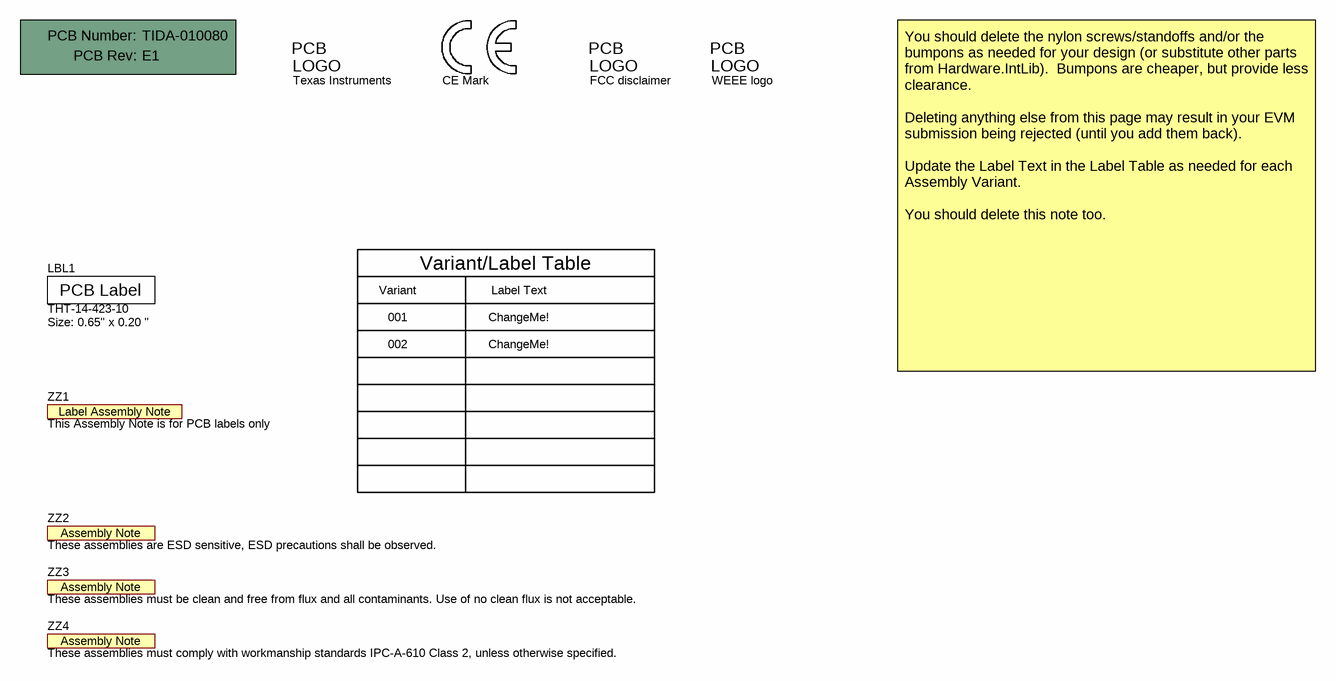
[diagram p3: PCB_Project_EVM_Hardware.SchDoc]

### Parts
!PCB1  Printed Circuit Board  (value not drawn)  (mechanical)
LBL1  THT-14-423-10  Note: Size: 0.65" x 0.20 "  [Label_650x200]
Logo1  CE Mark  [CE_Mark_5mm]  (no BOM)
Logo2  Texas Instruments  [TI_Stacked_Overlay_Small]  (no BOM)
Logo3  FCC disclaimer  [FCC_disclaimer]  (no BOM)
Logo4  WEEE logo  [WEEE_Minimum]  (no BOM)
ZZ1  This Assembly Note is for PCB labels only  [AssemblyNoteLabel]  (no BOM)
ZZ2  These assemblies are ESD sensitive, ESD precautions shall be observed.  [AssemblyNote]  (no BOM)
ZZ3  These assemblies must be clean and free from flux and all contaminants. Use of no clean flux is not acceptable.  [AssemblyNote]  (no BOM)
ZZ4  These assemblies must comply with workmanship standards IPC-A-610 Class 2, unless otherwise specified.  [AssemblyNote]  (no BOM)

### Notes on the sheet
- Variant
- Variant/Label Table
- Label Text
- 001
- 002
- ChangeMe!
- You should delete the nylon screws/standoffs and/or the bumpons as needed for your design (or substitute other parts from Hardware.IntLib).  Bumpons are cheaper, but provide less clearance.
  Deleting anything else from this page may result in your EVM submission being rejected (until you add them back).
  Update the Label Text in the Label Table as needed for each Assembly Variant.
  You should delete this note too.

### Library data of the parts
!PCB1 = CMP-0003618-2: Manufacturer: Any; PartNumber: TIDA-010080
LBL1 = CMP-0003625-1: Thermal Transfer Printable Labels, 0.650" W x 0.200" H - 10,000 per roll; Manufacturer: Brady; CompType: Label
Logo1 = CMP-0074844-1: SymbolCreator: a0412235
Logo2 = CMP-0074838-1: Texas Instrument Corporate Signature; SymbolCreator: a0412235; Lib Reference: TI_Logo; Library Reference: Logo
Logo3 = CMP-0074847-1: FCC_disclaimer; Library Reference: Logo
Logo4 = CMP-0074769-1
ZZ1 = CMP-0003616-3
ZZ2 = CMP-0077236-1
ZZ3 = CMP-0077237-1
ZZ4 = CMP-0077238-1

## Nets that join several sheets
390V: PFC (7 pins), LLC (Q5.2 R51.2)
PGND: PFC (34 pins), LLC (25 pins)
Pri_15V: PFC (10 pins), LLC (C52.1 C53.1 U7.3 U9.4)
Sec_15V: PFC (J2.10), LLC (5 pins)
SGND: PFC (J2.11 J2.12), LLC (33 pins)

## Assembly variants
001: not fitted FID1 FID2 FID3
